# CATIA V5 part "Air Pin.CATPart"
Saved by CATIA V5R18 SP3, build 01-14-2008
Part number: Connector Bar
Bounding box of the stored display mesh (mm): x -9.997 to 9.997, y 0 to 570, z -9.997 to 9.997
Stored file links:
  E:\#00 CATIA V5 Movie\#03 CATIA V5 Data\#07 KIN\Balance Unit (1)\Air Pin.CATPart
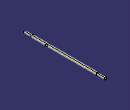
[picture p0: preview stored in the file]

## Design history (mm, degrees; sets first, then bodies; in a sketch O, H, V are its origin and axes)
Body1 (main body)
  Sketch1 on yz-plane, origin (0, 0, 0), H (0, 1, 0), V (0, 0, 1)
    line L1 (0, 0) -> (0, 8)
    line L2 (0, 8) -> (55, 8)
    line L3 (55, 8) -> (55, 10)
    line L4 (55, 10) -> (515, 10)
    line L5 (515, 10) -> (515, 8)
    line L6 (515, 8) -> (570, 8)
    line L7 (570, 8) -> (570, 0)
    point P7 (570, 0)
    distance L1 L3 = 55
    distance L7 L5 = 55
    length L4 = 460
    distance H L2 = 8
    distance L4 H = 10
    distance L6 H = 8
    vertical: L1 V, L3 V, L5 V, L7 V
    horizontal: L2 H, L4 H, L6 H
    coincidence: P7 H
  Shaft1: profile Sketch1, axis Sketch1.H, angle 360
  Sketch2 on xy-plane, origin (0, 0, 0), H (1, 0, 0), V (0, 1, 0)
    point P1 (-33.7472, 170)
    line L1 (-33.7472, 170) -> (-8, 170)
    line L2 (-8, 170) -> (-8, 155)
    line L3 (-8, 155) -> (-33.7472, 155)
    line L4 (-33.7472, 155) -> (-33.7472, 170)
    point P2 (-8, 170)
    point P3 (-8, 155)
    point P4 (-33.7472, 155)
    reference projected line E1 (-8, 55) -> (8, 55) from edge [face of Shaft1 from Sketch1.L2 | face of Shaft1 from Sketch1.L3]
    point P5 (33.7472, 155)
    point P6 (8, 155)
    point P7 (8, 170)
    point P8 (33.7472, 170)
    line L5 (33.7472, 155) -> (33.7472, 170)
    line L6 (8, 155) -> (33.7472, 155)
    line L7 (8, 170) -> (8, 155)
    line L8 (33.7472, 170) -> (8, 170)
    distance L3 E1 = 100
    distance L3 L1 = 15
    distance L7 L2 = 16
    horizontal: L1 H, L3 H
    vertical: L2 V, L4 V
    symmetry: P4 P5 V, P3 P6 V, P2 P7 V, P1 P8 V, L4 L5 V, L3 L6 V, L2 L7 V, L1 L8 V
  Pocket1: profile Sketch2, direction (0, 0, -1), length 20, mirrored extent
  Chamfer1: length 0.5, second length 0.5, on edge [face of Shaft1 from Sketch1.L6 | face of Shaft1 from Sketch1.L7]; face of Shaft1 from Sketch1.L1; edge [face of Shaft1 from Sketch1.L3 | face of Shaft1 from Sketch1.L4]; edge [face of Shaft1 from Sketch1.L4 | face of Shaft1 from Sketch1.L5]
